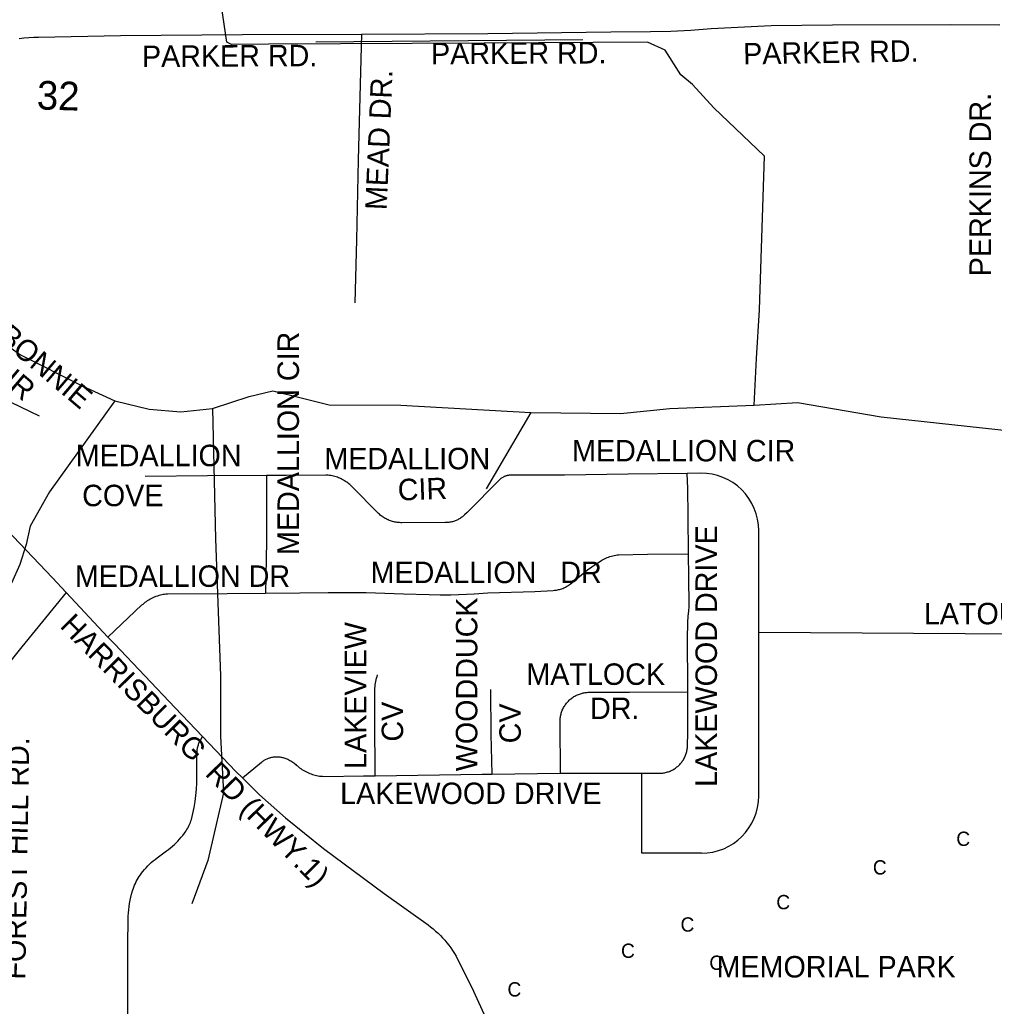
# Model space of a CAD drawing. Extents: x 1670563 to 1761545, y 515755 to 578944.
# Drawn here: x 1699015 to 1702422, y 535500 to 538948 of the extents above; entities that cross this region are included whole.
import ezdxf

# ---------------------------------------------------------------- set-up
doc = ezdxf.new("R2010")
doc.units = 0
for name, color, linetype in [('5_sectionlines', 7, 'Continuous'), ('62_text', 7, 'Continuous'), ('CEMETERY', 7, 'Continuous'), ('Cross', 7, 'Continuous'), ('SHP_LINE', 7, 'Continuous'), ('STREETCL', 7, 'Continuous'), ('STRNAMES', 7, 'Continuous')]:
    doc.layers.add(name, color=color, linetype=linetype)

msp = doc.modelspace()

# ---------------------------------------------------------------- linework, layer by layer
at = {"layer": '5_sectionlines'}
msp.add_line((1700050.1, 538870.2), (1700983.5, 538878.5), dxfattribs=at)
at = {"layer": 'SHP_LINE'}
for points in [[(1701618, 538471), (1701441, 538640), (1701367, 538721), (1701326, 538755), (1701271, 538842), (1701210, 538870), (1700638, 538866), (1699884, 538863), (1699755, 538861), (1699739, 538870), (1699697, 539154)], [(1701582, 537601), (1701590, 537764), (1701601, 537934), (1701618, 538471)], [(1698066, 538235), (1698275, 538228), (1698368, 538208), (1698388, 538202), (1698492, 538122), (1698588, 538024), (1698688, 537996), (1698770, 537948), (1698860, 537889), (1699017, 537777), (1699233, 537669), (1699347, 537616)], [(1699689, 537589), (1699817, 537631), (1699900, 537651), (1700003, 537625), (1700097, 537602), (1700347, 537601), (1700802, 537575)], [(1699347, 537616), (1699119, 537298), (1699051, 537178), (1699037, 537114), (1699015, 537044), (1698986, 536979)], [(1699347, 537616), (1699467, 537587), (1699578, 537578), (1699689, 537589)], [(1700802, 537575), (1701115, 537572), (1701287, 537589), (1701582, 537601)], [(1701582, 537601), (1701734, 537610), (1702026, 537560), (1702531, 537505), (1702744, 537472), (1702868, 537447)], [(1699689, 537589), (1699699, 537134), (1699717, 536655), (1699717, 536444), (1699727, 536246), (1699672, 536010), (1699616, 535858)], [(1700802, 537575), (1700646, 537308)]]:
    msp.add_lwpolyline(points, dxfattribs=at)
at = {"layer": 'STREETCL'}
for p, q in [((1701395.8, 537363), (1701348.6, 537362.4)), ((1701598.1, 536235.1), (1701598.1, 537163)), ((1701598.1, 536807.7), (1704226.3, 536789.3)), ((1701189.3, 536035.1), (1701189.3, 536315.4)), ((1701398.1, 536035.1), (1701189.3, 536035.1))]:
    msp.add_line(p, q, dxfattribs=at)
for points in [[(1700209.5, 538897.4), (1700651.3, 538899.8), (1701080.9, 538905.4), (1701220.1, 538906.8), (1701290.7, 538908.4), (1701361.3, 538911.8), (1701431.7, 538917), (1701642.3, 538927.6), (1701856.6, 538930.4), (1702270.1, 538930.8), (1702441.4, 538930.6)], [(1699012.9, 538882.5), (1699029.8, 538884.6), (1699046.7, 538886.1), (1699063.7, 538887), (1699080.7, 538887.4), (1699366.6, 538892.9), (1699793.9, 538895.7), (1700209.5, 538897.4)], [(1700209.5, 538897.4), (1700203.2, 538634.2), (1700198.1, 538457.7), (1700192, 538178.7), (1700185.8, 537958)], [(1698656.3, 537773.4), (1698678.3, 537758.2), (1699083.2, 537563.6)], [(1698743.5, 537401), (1698770.3, 537374.4), (1698796.4, 537347.1), (1698821.9, 537319.2), (1698946.1, 537189.6), (1699129, 536997), (1699177, 536946)], [(1699877.3, 537354.9), (1699671.2, 537354.4), (1699453, 537351.6)], [(1699877.3, 537354.9), (1699877.3, 537124.8), (1699873.6, 536943.9)], [(1701348.6, 537362.4), (1701142.4, 537360.1), (1700919.3, 537356.5), (1700734.4, 537356.5), (1700732.3, 537356.5), (1700730.1, 537356.4), (1700727.9, 537356.2), (1700725.8, 537355.9), (1700723.7, 537355.6), (1700721.5, 537355.2), (1700719.4, 537354.8), (1700717.3, 537354.2), (1700715.3, 537353.6), (1700713.2, 537352.9), (1700711.2, 537352.2), (1700709.2, 537351.4), (1700707.2, 537350.5), (1700705.3, 537349.6), (1700703.3, 537348.6), (1700701.5, 537347.5), (1700699.6, 537346.3), (1700697.8, 537345.2), (1700696.1, 537343.9), (1700694.3, 537342.6), (1700692.7, 537341.2), (1700578.5, 537225.8), (1700569.8, 537217.3), (1700567.5, 537215), (1700565.1, 537212.9), (1700562.6, 537210.8), (1700560, 537208.9), (1700557.3, 537207), (1700554.6, 537205.2), (1700551.9, 537203.5), (1700549.1, 537202), (1700546.2, 537200.5), (1700543.3, 537199.1), (1700540.3, 537197.8), (1700537.3, 537196.6), (1700534.2, 537195.5), (1700531.1, 537194.6), (1700528, 537193.7), (1700524.9, 537193), (1700521.7, 537192.3), (1700518.5, 537191.8), (1700515.3, 537191.4), (1700512, 537191.1), (1700508.8, 537190.9), (1700505.6, 537190.8), (1700502.3, 537190.8), (1700350.6, 537190.1), (1700346.6, 537190.2), (1700342.5, 537190.4), (1700338.4, 537190.7), (1700334.4, 537191.2), (1700330.4, 537191.8), (1700326.4, 537192.5), (1700322.4, 537193.4), (1700318.4, 537194.5), (1700314.5, 537195.6), (1700310.7, 537196.9), (1700306.9, 537198.3), (1700303.1, 537199.9), (1700299.4, 537201.6), (1700295.7, 537203.4), (1700292.1, 537205.3), (1700288.6, 537207.4), (1700285.2, 537209.5), (1700281.8, 537211.8), (1700278.5, 537214.2), (1700275.3, 537216.8), (1700272.2, 537219.4), (1700269.2, 537222.1), (1700175.6, 537316.8), (1700172.3, 537320.1), (1700168.9, 537323.2), (1700165.4, 537326.2), (1700161.7, 537329.1), (1700158, 537331.8), (1700154.2, 537334.4), (1700150.3, 537336.9), (1700146.3, 537339.2), (1700142.2, 537341.5), (1700138.1, 537343.5), (1700133.9, 537345.4), (1700129.6, 537347.2), (1700125.2, 537348.8), (1700120.9, 537350.3), (1700116.4, 537351.6), (1700111.9, 537352.8), (1700107.4, 537353.8), (1700102.9, 537354.6), (1700098.3, 537355.3), (1700093.7, 537355.9), (1700089.1, 537356.3), (1700084.5, 537356.5), (1699947, 537355.1), (1699877.3, 537354.9)], [(1701352.9, 537081.2), (1701351.2, 537213.6), (1701350.5, 537309.6), (1701348.6, 537362.4)], [(1699873.6, 536943.9), (1699994.2, 536944.5), (1700093.3, 536946.7), (1700225.6, 536946), (1700356.4, 536941.8), (1700446.5, 536939), (1700484.1, 536938.3), (1700521.7, 536938.3), (1700603.5, 536941.8), (1700651.5, 536944.6), (1700815.8, 536950.2), (1700880.1, 536953.7), (1700883.8, 536954), (1700887.6, 536954.4), (1700891.3, 536954.9), (1700895, 536955.5), (1700898.7, 536956.3), (1700902.3, 536957.2), (1700905.9, 536958.3), (1700909.5, 536959.4), (1700913, 536960.7), (1700916.5, 536962.1), (1700919.9, 536963.7), (1700923.3, 536965.3), (1700926.6, 536967.1), (1700929.9, 536969), (1700933.1, 536970.9), (1700936.2, 536973), (1700939.2, 536975.2), (1700985.9, 537013.5), (1701000.2, 537024.9), (1701014.8, 537035.8), (1701029.9, 537046.2), (1701045.2, 537056.1), (1701049.7, 537058.8), (1701054.2, 537061.3), (1701058.9, 537063.7), (1701063.6, 537065.9), (1701068.4, 537068), (1701073.2, 537069.9), (1701078.1, 537071.6), (1701083.1, 537073.1), (1701088.1, 537074.5), (1701093.2, 537075.7), (1701098.3, 537076.8), (1701103.4, 537077.7), (1701108.5, 537078.4), (1701209.5, 537079.8), (1701353.1, 537081.2)], [(1701350.1, 536599), (1701349.7, 536803), (1701350, 536822.8), (1701350.7, 536842.5), (1701352.1, 536862.3), (1701353.9, 536881.9), (1701354.4, 536886.6), (1701354.6, 536891.3), (1701354.7, 536896), (1701354.6, 536900.7), (1701353.9, 536999.5), (1701352.9, 537081.2)], [(1699177, 536946), (1699021.9, 536756.3), (1698957, 536674.6), (1698953, 536669.3), (1698949.1, 536663.9), (1698945.4, 536658.4), (1698942, 536652.7), (1698938.7, 536646.9), (1698935.6, 536641), (1698932.8, 536635), (1698930.1, 536628.9), (1698927.7, 536622.7), (1698925.4, 536616.4), (1698923.4, 536610.1), (1698921.7, 536603.7), (1698920.1, 536597.2), (1698918.8, 536590.7), (1698917.7, 536584.1), (1698916.8, 536577.5), (1698916.2, 536570.9), (1698917, 536338.4), (1698919.1, 536117.7)], [(1699177, 536946), (1699323.4, 536790.4)], [(1699323.4, 536790.4), (1699442.3, 536902.6), (1699446, 536905.9), (1699449.8, 536909.1), (1699453.6, 536912.2), (1699457.6, 536915.2), (1699461.7, 536918), (1699465.8, 536920.6), (1699470.1, 536923.1), (1699474.4, 536925.5), (1699478.8, 536927.7), (1699483.3, 536929.8), (1699487.8, 536931.7), (1699492.4, 536933.5), (1699497.1, 536935.1), (1699501.8, 536936.5), (1699506.6, 536937.8), (1699511.4, 536939), (1699516.3, 536939.9), (1699521.1, 536940.7), (1699526, 536941.3), (1699530.9, 536941.8), (1699740.4, 536943.2), (1699873.6, 536943.9)], [(1699323.4, 536790.4), (1699345.9, 536766.4), (1699558.1, 536542.9), (1699654.1, 536442.4)], [(1700257.7, 536305.7), (1700256, 536504.2), (1700256, 536600), (1700256.1, 536605.9), (1700256.4, 536611.9), (1700256.9, 536617.8), (1700257.6, 536623.7), (1700258.5, 536629.6), (1700259.6, 536635.4), (1700260.9, 536641.2), (1700262.4, 536646.9), (1700264, 536652.6), (1700265.9, 536658.3)], [(1700660.4, 536607.5), (1700661.9, 536450.8), (1700665.1, 536311.7)], [(1700905.3, 536314.7), (1700903.8, 536490), (1700903.7, 536493.5), (1700903.7, 536497.1), (1700903.8, 536500.6), (1700904.1, 536504.1), (1700904.4, 536507.6), (1700904.9, 536511.1), (1700905.5, 536514.6), (1700906.3, 536518.1), (1700907.1, 536521.5), (1700908.1, 536524.9), (1700909.2, 536528.3), (1700910.4, 536531.6), (1700911.7, 536534.9), (1700913.1, 536538.1), (1700914.6, 536541.3), (1700916.3, 536544.4), (1700918, 536547.5), (1700919.9, 536550.5), (1700921.9, 536553.4), (1700923.9, 536556.3), (1700926.1, 536559.1), (1700928.3, 536561.8), (1700930.7, 536564.4), (1700933.1, 536567), (1700935.6, 536569.5), (1700938.2, 536571.8), (1700940.9, 536574.1), (1700943.7, 536576.3), (1700946.5, 536578.4), (1700949.4, 536580.4), (1700952.4, 536582.3), (1700955.5, 536584.1), (1700958.6, 536585.8), (1700961.7, 536587.4), (1700964.9, 536588.9), (1700968.2, 536590.2), (1700971.5, 536591.5), (1700974.9, 536592.6), (1700978.2, 536593.6), (1700981.7, 536594.5), (1700985.1, 536595.3), (1700988.6, 536595.9), (1700992.1, 536596.5), (1700995.6, 536596.9), (1700999.1, 536597.2), (1701002.6, 536597.4), (1701006.1, 536597.4), (1701146.7, 536598.1), (1701350.2, 536599)], [(1700905.3, 536314.7), (1700963.4, 536315.4), (1701238.7, 536315.4), (1701242.1, 536315.1), (1701245.5, 536314.8), (1701248.9, 536314.7), (1701252.3, 536314.7), (1701255.8, 536314.8), (1701259.2, 536315.1), (1701262.6, 536315.4), (1701266, 536315.9), (1701269.3, 536316.5), (1701272.7, 536317.2), (1701276, 536318), (1701279.3, 536319), (1701282.6, 536320), (1701285.8, 536321.2), (1701289, 536322.4), (1701292.1, 536323.8), (1701295.2, 536325.3), (1701298.2, 536326.9), (1701301.2, 536328.6), (1701304.1, 536330.4), (1701306.9, 536332.3), (1701309.7, 536334.3), (1701312.4, 536336.4), (1701315.1, 536338.6), (1701317.6, 536340.9), (1701320.1, 536343.2), (1701322.5, 536345.7), (1701324.8, 536348.2), (1701327, 536350.8), (1701329.1, 536353.5), (1701331.2, 536356.2), (1701333.1, 536359.1), (1701334.9, 536361.9), (1701336.7, 536364.9), (1701338.3, 536367.9), (1701339.8, 536371), (1701341.3, 536374.1), (1701342.6, 536377.2), (1701343.8, 536380.4), (1701344.9, 536383.7), (1701345.8, 536387), (1701346.7, 536390.3), (1701347.5, 536393.6), (1701348.1, 536397), (1701348.6, 536400.4), (1701349, 536403.8), (1701350.4, 536462.2), (1701350.1, 536599)], [(1699393.1, 535472.1), (1699393.1, 535715), (1699394.3, 535804.5), (1699394.5, 535815.6), (1699395.1, 535826.7), (1699396, 535837.8), (1699397.3, 535848.9), (1699398.9, 535859.9), (1699400.9, 535870.8), (1699403.3, 535881.7), (1699405.9, 535892.5), (1699409, 535903.2), (1699411.2, 535909.9), (1699413.6, 535916.5), (1699416.2, 535923.1), (1699419.1, 535929.5), (1699422.2, 535935.9), (1699425.5, 535942.1), (1699429, 535948.2), (1699432.7, 535954.2), (1699436.6, 535960.1), (1699440.7, 535965.8), (1699445, 535971.4), (1699450.6, 535978), (1699456.3, 535984.4), (1699462.3, 535990.5), (1699468.4, 535996.5), (1699474.8, 536002.4), (1699481.3, 536008), (1699488, 536013.4), (1699494.8, 536018.6), (1699527.8, 536043.2), (1699535, 536048.3), (1699542, 536053.7), (1699548.8, 536059.3), (1699555.4, 536065.1), (1699561.8, 536071.2), (1699567.9, 536077.5), (1699573.9, 536083.9), (1699579.6, 536090.6), (1699585.1, 536097.5), (1699590.4, 536104.6), (1699593.6, 536109), (1699596.6, 536113.6), (1699599.4, 536118.3), (1699602.1, 536123), (1699604.7, 536127.8), (1699607.1, 536132.8), (1699609.3, 536137.7), (1699611.4, 536142.8), (1699613.3, 536147.9), (1699615, 536153.1), (1699620, 536173.9), (1699624.2, 536194.8), (1699627.8, 536215.9), (1699630.5, 536237.1), (1699632.5, 536258.4), (1699633.8, 536279.7), (1699634.5, 536384.3), (1699634.6, 536387.6), (1699634.8, 536390.9), (1699635.1, 536394.2), (1699635.5, 536397.4), (1699636.1, 536400.7), (1699636.7, 536403.9), (1699637.5, 536407.1), (1699638.3, 536410.3), (1699639.3, 536413.5), (1699640.3, 536416.6), (1699641.5, 536419.7), (1699642.7, 536422.8), (1699644.1, 536425.8), (1699654.1, 536442.4)], [(1699654.1, 536442.4), (1699769.9, 536321.1), (1699793.3, 536298.1)], [(1699793.3, 536298.1), (1699860, 536353), (1699862.2, 536354.8), (1699864.6, 536356.5), (1699866.9, 536358.2), (1699869.4, 536359.7), (1699871.8, 536361.2), (1699874.4, 536362.6), (1699876.9, 536363.9), (1699879.5, 536365.1), (1699882.2, 536366.2), (1699884.9, 536367.3), (1699887.6, 536368.2), (1699890.4, 536369), (1699893.2, 536369.8), (1699896, 536370.4), (1699898.8, 536371), (1699901.6, 536371.4), (1699904.5, 536371.8), (1699907.4, 536372.1), (1699910.2, 536372.2), (1699913.1, 536372.3), (1699916, 536372.3), (1699918.9, 536372.2), (1699921.7, 536371.9), (1699924.6, 536371.6), (1699927.5, 536371.2), (1699930.3, 536370.7), (1699933.1, 536370.1), (1699935.9, 536369.3), (1699938.7, 536368.5), (1699941.4, 536367.6), (1699945.1, 536366.3), (1699948.8, 536364.8), (1699952.4, 536363.2), (1699955.9, 536361.4), (1699959.4, 536359.6), (1699962.9, 536357.6), (1699966.2, 536355.5), (1699969.5, 536353.3), (1699972.7, 536350.9), (1699975.8, 536348.5), (1699978.8, 536346), (1699981.8, 536343.3), (1699985.5, 536339.9), (1699989.4, 536336.7), (1699993.4, 536333.5), (1699997.4, 536330.6), (1700001.6, 536327.7), (1700005.9, 536325), (1700010.3, 536322.5), (1700014.7, 536320.1), (1700019.2, 536317.8), (1700023.9, 536315.7), (1700028.5, 536313.8), (1700033.3, 536312), (1700038.1, 536310.4), (1700042.9, 536309), (1700047.8, 536307.7), (1700052.7, 536306.6), (1700057.7, 536305.7), (1700062.7, 536304.9), (1700067.7, 536304.3), (1700072.8, 536303.9), (1700077.8, 536303.7), (1700216.3, 536305), (1700257.7, 536305.7)], [(1699793.3, 536298.1), (1699853.4, 536239.2), (1699943.7, 536159), (1700076.4, 536051.7), (1700288.5, 535894), (1700442.2, 535784.3), (1700451.3, 535777.5), (1700460.2, 535770.4), (1700468.9, 535763.1), (1700477.3, 535755.4), (1700485.5, 535747.5), (1700493.3, 535739.3), (1700500.9, 535730.8), (1700508.2, 535722.1), (1700515.2, 535713.2), (1700521.9, 535704), (1700528.3, 535694.6), (1700534.4, 535685), (1700540.1, 535675.2), (1700545.5, 535665.2), (1700595.1, 535565.4), (1700648.6, 535447.9)], [(1700257.7, 536305.7), (1700631.7, 536311.2), (1700665.1, 536311.7)], [(1700665.1, 536311.7), (1700905.3, 536314.7)]]:
    msp.add_lwpolyline(points, dxfattribs=at)
for centre, start, end in [((1701398.1, 537163), 0, 90.641), ((1701398.1, 536235.1), 270, 0)]:
    msp.add_arc(centre, 200, start, end, dxfattribs=at)

# ---------------------------------------------------------------- texts
at = {"layer": '62_text'}
msp.add_text('32', height=100, rotation=358.1866, dxfattribs=at).set_placement((1699073.7, 538634.8))
at = {"layer": 'CEMETERY'}
msp.add_text('MEMORIAL PARK', height=75, dxfattribs=at).set_placement((1701450.9, 535600.8))
at = {"layer": 'Cross'}
for p in [(1702289.1, 536060.5), (1701997.4, 535960.6), (1701659.8, 535839.2), (1701324.9, 535761), (1701116.9, 535669.2), (1701425.6, 535627.3), (1700719.9, 535534.3)]:
    msp.add_text('C', height=50, dxfattribs=at).set_placement(p)
at = {"layer": 'STRNAMES'}
for s, rotation, p in [('PARKER RD.', 0.2932, (1700453.1, 538792.1)), ('PARKER RD.', 1, (1701544.5, 538791.3)), ('PARKER RD.', 0.2932, (1699442.4, 538782.5)), ('MEAD DR.', 87.5617, (1700297.6, 538281.6)), ('PERKINS DR.', 90, (1702410, 538051.4)), ('BONNIE ', 319.6569, (1698934.6, 537832)), ('MEDALLION CIR', 90, (1699991, 537077.3)), ('CIR', 319.6569, (1698896.7, 537723.6)), ('CIR', 1.9538, (1700337.5, 537267.5)), ('LAKEWOOD DRIVE', 90, (1701452.2, 536267)), ('WOODDUCK ', 90, (1700614.6, 536321.5)), ('HARRISBURG  RD (HWY.1)', 314.5032, (1699152, 536826.4)), ('LAKEVIEW ', 90, (1700226.2, 536329.8)), ('CV', 90, (1700355.2, 536425.2)), ('CV', 90, (1700766.5, 536419)), ('FOREST HILL RD.', 89.0765, (1699034.6, 535593.1))]:
    msp.add_text(s, height=75, rotation=rotation, dxfattribs=at).set_placement(p)
for s, p in [('MEDALLION', (1699210.7, 537387.6)), ('MEDALLION CIR', (1700945.8, 537404.4)), ('MEDALLION', (1700079.9, 537376.7)), (' COVE', (1699205.3, 537247.8)), ('MEDALLION   DR', (1700241.4, 536979)), ('MEDALLION DR', (1699207.7, 536965.9)), ('LATOURETTE DRIVE', (1702175.5, 536835.1)), ('MATLOCK ', (1700786, 536623.4)), ('DR.', (1701008.5, 536504.1)), ('LAKEWOOD DRIVE', (1700135, 536206.9))]:
    msp.add_text(s, height=75, dxfattribs=at).set_placement(p)

doc.saveas('drawing.dxf')
